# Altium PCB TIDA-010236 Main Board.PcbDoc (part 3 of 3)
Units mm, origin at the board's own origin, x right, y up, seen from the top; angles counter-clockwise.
Board outline 180 x 120 mm, 2 copper layers (Top Layer, Bottom Layer), stack 1.571 mm thick; 265 components, 145 nets, 704 pads, 547 vias.
Unrouted connection lines stored in the file: 155.
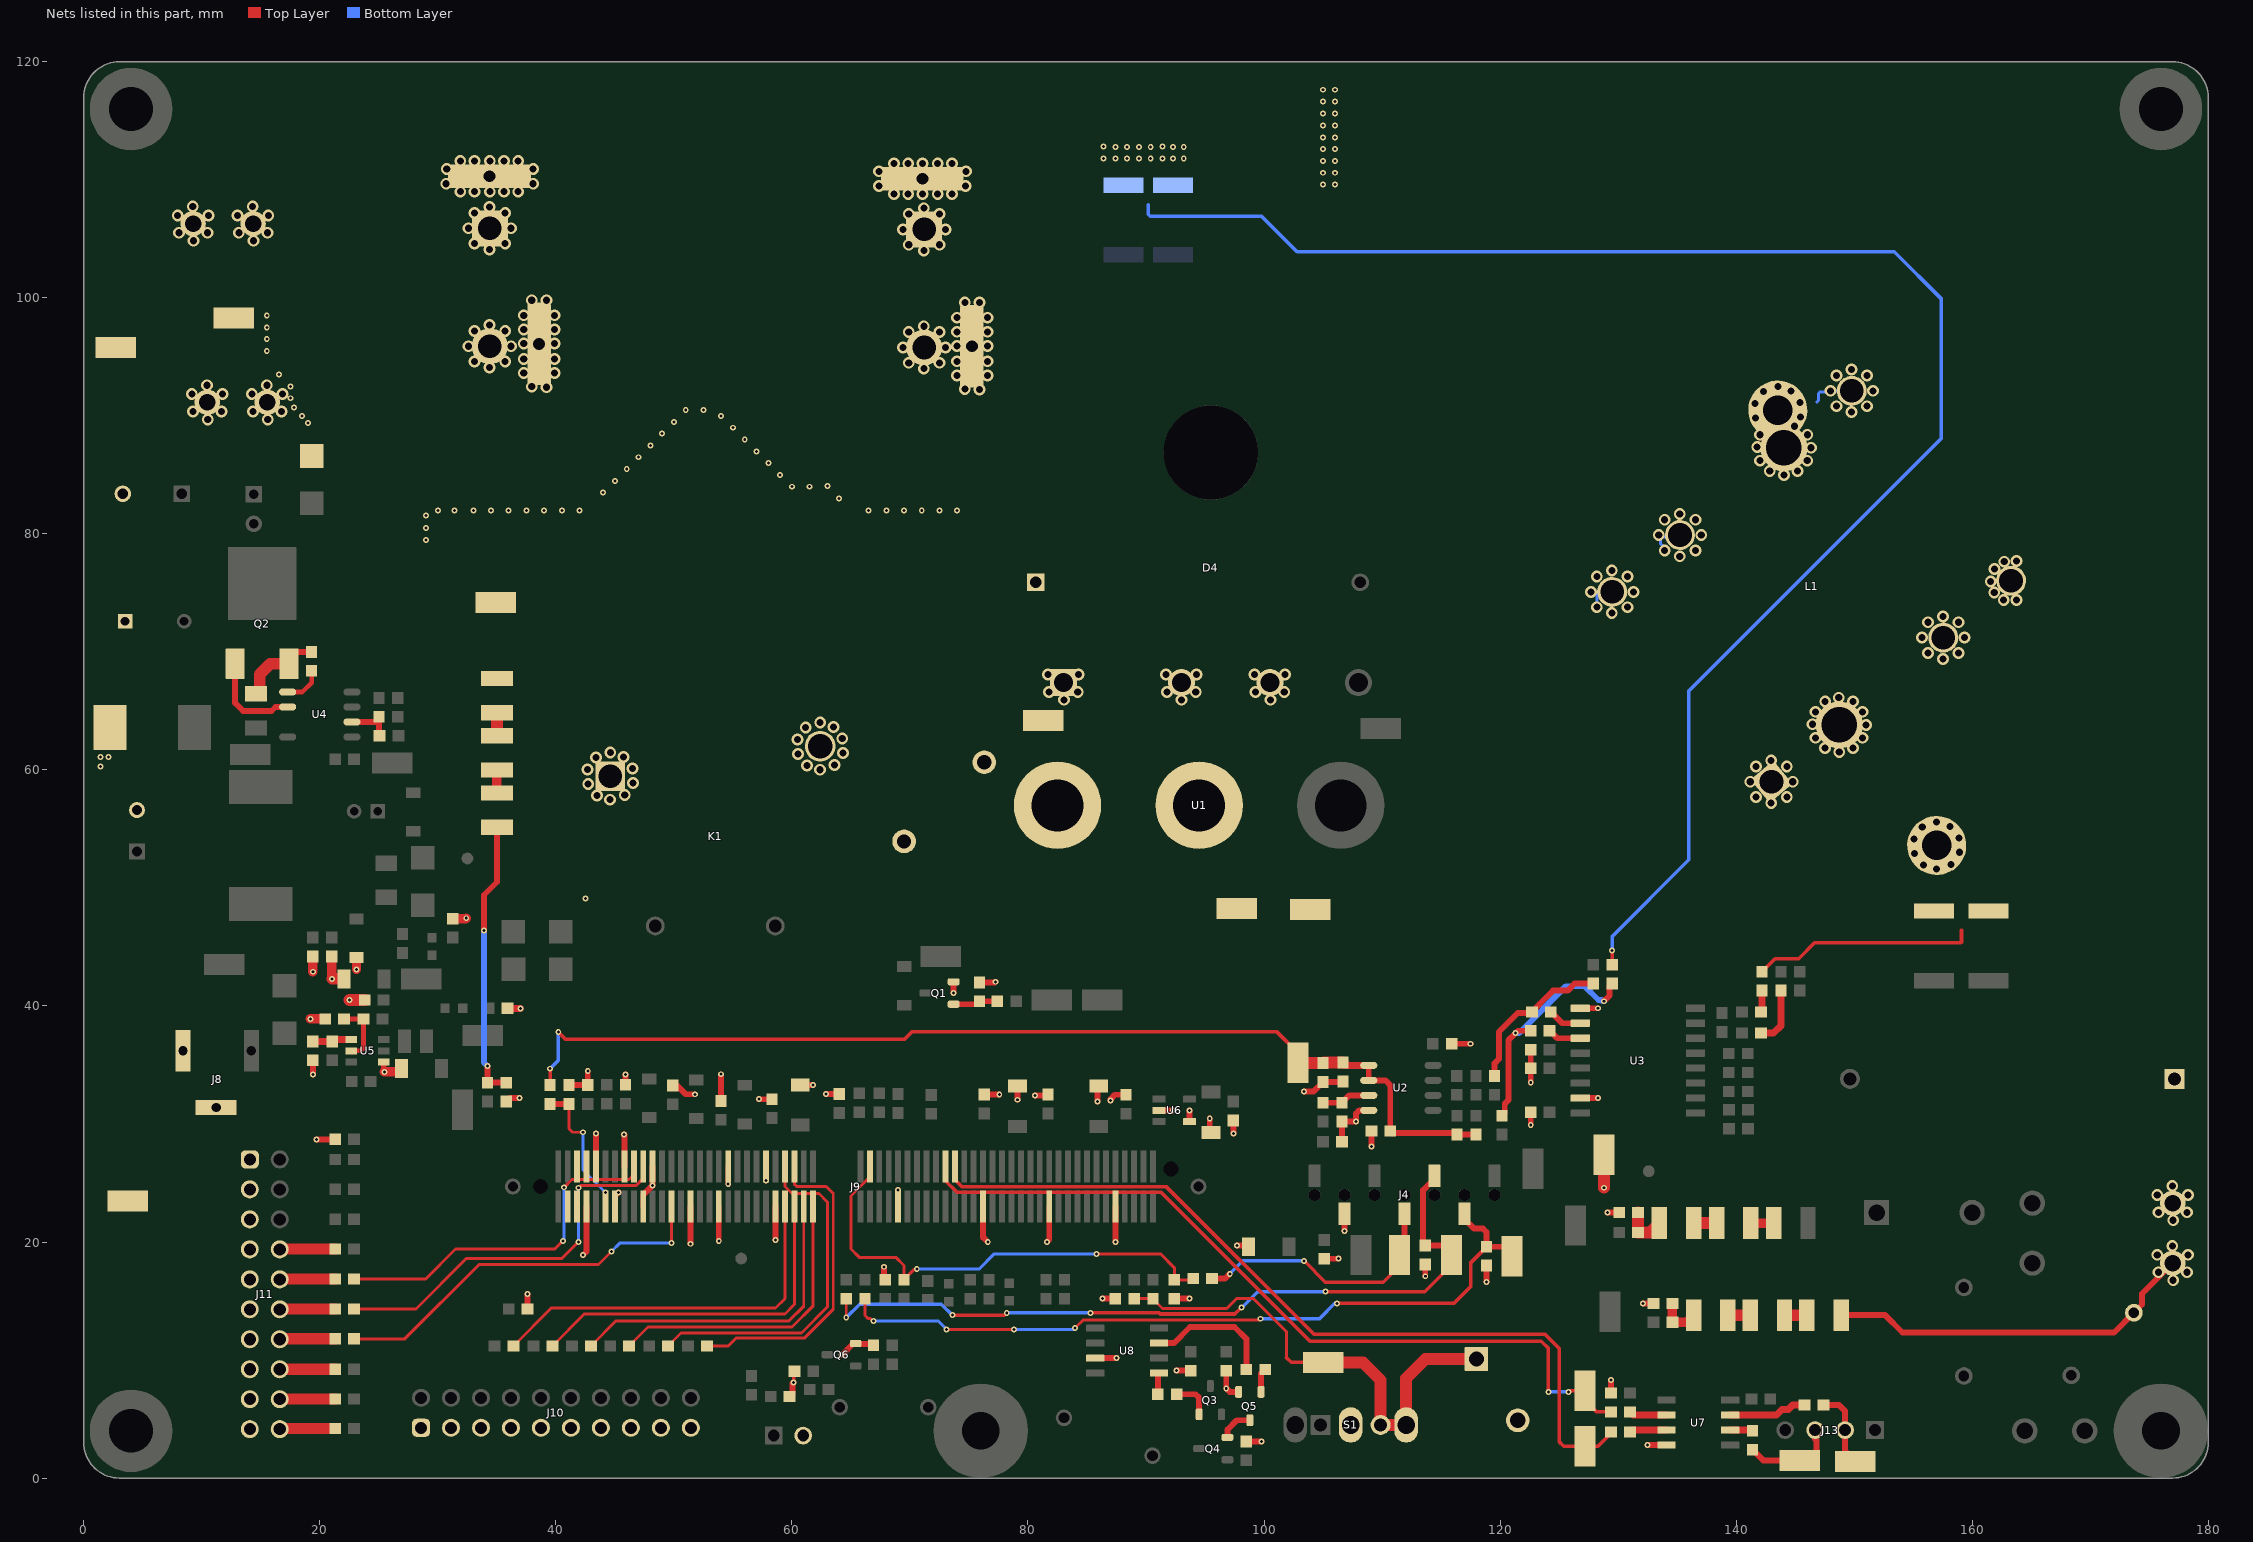
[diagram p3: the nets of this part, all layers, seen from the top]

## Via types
v1: diameter 1, hole 0.6, Top Layer to Bottom Layer, 286 vias
v2: diameter 0.5, hole 0.25, Top Layer to Bottom Layer, 261 vias

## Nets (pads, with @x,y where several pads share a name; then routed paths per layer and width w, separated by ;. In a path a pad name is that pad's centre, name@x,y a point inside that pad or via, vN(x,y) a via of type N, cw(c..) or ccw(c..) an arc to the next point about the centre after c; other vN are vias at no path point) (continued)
NetJ11_8: J11.8 R68.2 | length 4.7
  Top Layer w0.95: J11.8@16.6,19.38 16.62,19.4 R68.2@21.3,19.4
NetJ11_10: J11.10 R66.2 | length 4.7
  Top Layer w0.95: J11.10@16.6,16.84 16.627,16.867 R66.2@21.3,16.867
NetJ11_12: J11.12 R64.2 | length 4.7
  Top Layer w0.95: J11.12@16.6,14.3 16.633,14.333 R64.2@21.3,14.333
NetJ11_14: J11.14 R62.2 | length 4.7
  Top Layer w0.95: J11.14@16.6,11.76 16.64,11.8 R62.2@21.3,11.8
NetJ11_16: J11.16 R60.2 | length 4.7
  Top Layer w0.95: J11.16@16.6,9.22 R60.2@21.3,9.22
NetJ11_18: J11.18 R59.2 | length 4.7
  Top Layer w0.95: J11.18@16.6,6.68 16.62,6.7 R59.2@21.3,6.7
NetJ11_20: J11.20 R56.2 | length 4.7
  Top Layer w0.95: J11.20@16.6,4.14 16.66,4.2 R56.2@21.3,4.2
NetL1_1: L1.1 L1.2 L1.3 L1.4 L2.1 L4.2 R7.2 R8.2 | length 18.9
  Top Layer w0.3: L4.2@142.2,42.9 143.3,44 145.3,44 146.65,45.35 159.05,45.35 159.1,45.4 159.1,46.4
  other v1: 156.975,51.6 155.875,51.95 158.225,52 155.125,52.925 158.925,53.025 155.075,54.15 158.875,54.25 155.775,55.175 158.125,55.225 157,55.6 142.975,57.2 141.7,57.7 144.3,57.7 141.2,59 144.8,59 141.7,60.3 144.3,60.3 142.975,60.8 148.745,61.525 147.545,61.85 149.895,61.85 146.72,62.725 150.72,62.725 151.025,63.821 146.475,63.875 146.725,64.925 150.725,64.925 147.55,65.8 149.9,65.8 148.7,66.125 157.525,69.413 156.25,69.913 158.85,69.913 155.75,71.213 159.35,71.213 156.25,72.513 158.85,72.513 157.525,73.013 162.675,74.4 163.75,74.4 161.875,75.025 161.575,75.975 161.9,77.025 162.725,77.65 163.75,77.7
NetL4_1: L4.1 R6.1 | length 1.8
  Top Layer w0.6: R6.1@142.1,39.5 142.2,39.6 L4.1@142.2,41.3
NetL5_1: L5.1 R9.1 | length 4.9
  Top Layer w0.6: R9.1@142.1,37.7 143.176,37.7 143.8,38.324 L5.1@143.8,41.3
NetQ1_1: Q1.1 R2.1 R3.2 | length 3.8
  Top Layer w0.5: Q1.1@73.7,40.15 75.644,40.15 R3.2@75.893,40.4 R2.1@77.4,40.4
NetQ2_1: Q2.1 U4.6 | length 8.2
  Top Layer w0.5: Q2.1@12.82,69 12.82,65.68 13.5,65 15.9,65 16.235,65.335 U4.6@17.268,65.335
NetQ2_3: Q2.3 R1.1 R37.1 | length 7.1
  Top Layer w0.5: Q2.3@17.38,69 17.38,69.48 17.9,70 R1.1@19.3,70
  Top Layer w1: R37.1@14.9,66.45 14.9,68.1 15.8,69 Q2.3@17.38,69
NetQ3_1: Q3.1 R82.2 | length 3.4
  Top Layer w0.5: R82.2@92.6,7.1 94.2,7.1 94.5,6.8 Q3.1@94.5,5.4
NetQ4_2: Q4.2 Q5.3 | length 2.9
  Top Layer w0.5: Q4.2@96.9,3.45 96.9,4.1 97.7,4.9 Q5.3@98.8,4.9
NetQ5_1: Q5.1 R84.2 | length 2
  Top Layer w0.5: Q5.1@99.75,7.3 99.75,8.85 R84.2@100.1,9.2
NetR1_2: R1.2 U4.5 | length 3.4
  Top Layer w0.4: U4.5@17.268,66.605 18.505,66.605 19.3,67.4 R1.2@19.3,68.4
NetR10_1: R10.1 R11.2 U2.3 | length 4.1
  Top Layer w0.5: R10.1@105,31.8 R11.2@106.6,31.8 107.227,32.426 U2.3@108.875,32.426
NetR12_1: R12.1 R18.2 U5.5 | length 5.3
  Top Layer w0.4: R18.2@22.05,38.9 R12.1@23.7,38.9 23.7,36.434 23.466,36.2 U5.5@22.662,36.2
NetR14_2: R14.2 R15.1 | length 1.9
  Top Layer w0.8: R15.1@141.25,21.6 R14.2@143.2,21.6
NetR15_2: R15.2 R16.1 | length 1.9
  Top Layer w1: R16.1@136.4,21.6 R15.2@138.35,21.6
NetR16_2: R16.2 R17.1 R21.2 | length 3.8
  Top Layer w1: R21.2@131.7,22.5 R17.1@131.7,20.8 132.7,20.8 R16.2@133.5,21.6
NetR19_1: R19.1 R20.2 R85.1 | length 13.6
  Top Layer w0.5: R19.1@119.541,34.075 119.541,35.151 119.9,35.51 119.9,37.8 121.5,39.4 122.625,39.4 122.95,39.725 122.95,39.75 123.35,40.15 123.35,40.161 124.489,41.3 125.725,41.3 126.325,41.9 R20.2@127.9,41.9
NetR23_1: R23.1 R24.2 R86.1 | length 20
  Top Layer w0.5: R23.1@120.175,30.7 120.4,30.925 120.4,31.723 120.7,32.023 120.7,37.088 v2@121.306,37.694 ; 121.512,37.9 R86.1@122.6,37.9 ; v2(128.8,40.4) 129.275,40.875 129.275,41.675 R24.2@129.5,41.9
  Bottom Layer w0.5: v2(121.3,37.7) 121.6,37.7 125.575,41.675 127.174,41.675 128.342,40.507 128.59,40.507 128.697,40.4 v2(128.8,40.4)
NetR26_2: R26.2 R27.1 | length 1.9
  Top Layer w1: R27.1@144.1,13.8 R26.2@146,13.8
NetR27_2: R27.2 R28.1 | length 1.9
  Top Layer w1: R28.1@139.3,13.8 R27.2@141.2,13.8
NetR28_2: R28.2 R29.1 R30.2 | length 3.6
  Top Layer w0.8: R30.2@134.6,14.8 R29.1@134.6,13.2 135.8,13.2 R28.2@136.4,13.8
NetR31_2: R31.2 R32.1 | length 1.9
  Top Layer w1: R32.1@35,62.9 R31.2@35,64.85
NetR32_2: R32.2 R33.1 | length 2
  Top Layer w0.8: R33.1@35,58.05 R32.2@35,60
NetR33_2: R33.2 R34.1 R35.2 | length 23.8
  Top Layer w0.5: v2(33.9,46.4) 33.9,49.4 35,50.5 R33.2@35,55.15 ; v2(34.2,34.9) R34.1@34.2,33.5 R35.2@35.8,33.5
  Bottom Layer w0.5: v2(33.9,46.4) 33.9,35.2 v2(34.2,34.9)
NetR36_1: R36.1 R39.2 U4.2 | length 3.4
  Top Layer w0.5: U4.2@22.718,64.065 24.935,64.065 25,64 25,62.95 R36.1@25.05,62.9
NetR40_1: R40.1 R42.2 U5.4 | length 3.3
  Top Layer w0.6: R42.2@19.4,37 R40.1@21.039,37 21.189,37.15 U5.4@22.662,37.15
NetR78_2: R78.2 U7.7 | length 6.7
  Top Layer w0.6: U7.7@139.5,5.335 143.415,5.335 143.9,5.82 144.42,5.82 144.8,6.2 R78.2@145.8,6.2
NetR79_2: R79.2 U7.2 | length 3.2
  Top Layer w0.6: R79.2@131,5.6 131.265,5.335 U7.2@134.1,5.335
NetR80_1: R80.1 U7.3 | length 3.2
  Top Layer w0.6: R80.1@131,3.9 131.165,4.065 U7.3@134.1,4.065
NetR81_1: R81.1 U7.6 | length 1.9
  Top Layer w0.6: U7.6@139.5,4.065 141.335,4.065 R81.1@141.4,4
NetR82_1: R82.1 U8.5 | length 1.8
  Top Layer w0.5: R82.1@91,7.1 91,8.795 U8.5@91.1,8.895
NetR84_1: R84.1 U8.7 | length 11
  Top Layer w0.5: U8.7@91.1,11.435 92.367,11.435 93.732,12.8 97.5,12.8 98.5,11.8 R84.1@98.5,9.2
NetR85_2: R85.2 U3.10 | length 2.9
  Top Layer w0.5: R85.2@124.3,39.5 124.325,39.5 124.55,39.275 124.55,39.25 125.263,38.537 U3.10@126.811,38.537
NetR86_2: R86.2 U3.11 | length 2.9
  Top Layer w0.5: R86.2@124.2,37.9 124.225,37.9 124.858,37.267 U3.11@126.811,37.267
NEU_Filtered: C64.1 C69.2 D4.2 D4.3 J3.1 R26.1 | length 31.7
  Top Layer w0.5: R26.1@148.9,13.8 152.634,13.8 154.099,12.335 172.035,12.335 C69.2@173.703,14.003 174.4,14.7 174.4,15.62 J3.1@177,18.22
  other v1: 177.04,16.763 175.79,17.438 178.215,17.438 175.69,18.913 178.29,18.913 176.965,19.663 177.04,21.843 175.79,22.518 178.215,22.518 175.69,23.993 178.29,23.993 176.965,24.743 93,65.943 100.54,65.943 91.79,66.618 94.215,66.618 99.29,66.618 101.715,66.618 91.69,68.093 94.29,68.093 99.19,68.093 101.79,68.093
  other v2: 105,109.6 106,109.6 105,110.6 106,110.6 105.014,111.6 106.014,111.6 105,112.6 106,112.6 105,113.6 106,113.6 105.014,114.6 106.014,114.6 105,115.636 106,115.636 105,116.636 106,116.636 105.014,117.636 106.014,117.636
On/Off: J6.1 pad.2@112.04,4.5 R72.1 R75.2 S1.3 TP30.1 | length 42.3
  Top Layer w0.25: R75.2@89,15.2 R72.1@90.6,15.2 ; 101.9,10.2 101.9,12.4 99.1,15.2 97.664,15.2 96.839,14.375 91.4,14.375 R72.1@90.6,15.175 ; R72.1@90.6,15.175 R72.1@90.6,15.2 ; R72.1@90.6,15.175 R72.1@90.6,15.2
  Top Layer w0.3: 101.9,10.2 102.3,9.8 TP30.1@105.039,9.8
  Top Layer w1: TP30.1@105.039,9.8 108.375,9.8 109.88,8.295 S1.3@109.88,4.5 pad.2@112.04,4.5 112.04,8.46 113.665,10.085 J6.1@118,10.085
PB+: C1.2 C2.2 C3.1 C4.1 D12.2 J5.1 K1.1 R31.1 RT1.1 TP2.1 TP3.1
  other v1: 44.585,57.48 43.485,57.83 45.835,57.88 42.735,58.805 46.535,58.905 42.685,60.03 46.485,60.13 43.385,61.055 45.735,61.105 44.61,61.48 10.5,89.7 15.58,89.7 9.25,90.375 11.675,90.375 14.33,90.375 16.755,90.375 9.15,91.85 11.75,91.85 14.23,91.85 16.83,91.85 75.9,92.225 74.65,92.275 39.2,92.425 37.95,92.475 10.425,92.6 15.505,92.6 73.975,93.425 76.575,93.425 37.275,93.625 39.875,93.625 71.175,94 34.375,94.1 69.9,94.5 72.5,94.5 33.1,94.6 35.7,94.6 73.975,94.625 76.575,94.625 37.275,94.825 39.875,94.825 69.4,95.8 73,95.8 32.6,95.9 36.2,95.9 73.975,95.925 76.575,95.925 37.275,96.125 39.875,96.125 69.9,97.1 72.5,97.1 73.975,97.125 76.575,97.125 33.1,97.2 35.7,97.2 37.275,97.325 39.875,97.325 71.175,97.6 34.375,97.7 73.975,98.325 76.575,98.325 37.275,98.525 39.875,98.525 74.65,99.6 75.9,99.6 37.95,99.8 39.2,99.8
  other v2: 29,79.5 29,80.5 29,81.55 30,82 31.4,82 33,82 34.5,82 35.996,82 37.5,82 39,82 40.5,82 42,82 66.5,82 68,82 69.505,82 71,82 72.5,82 74,82 64,83 44,83.5 60,84 61.5,84 63,84.05 45,84.5 59,85 46,85.5 58,86 47,86.5 57,87 48,87.5 56,88 49,88.5 55,89 19,89.4 50,89.5 18.5,90 54,90 51,90.5 52.5,90.5 17.8,90.7 17.5,91.5 17.5,92.5 16.54,93.5 15.5,95.5 15.5,96.5 15.5,97.5 15.5,98.5
PB-: C1.1 C2.1 C3.2 C4.2 C6.2 C7.2 C9.2 C13.2 C15.2 C16.2 C17.2 C19.2 C20.1 C22.2 C23.1 C24.2 C26.2 C27.2 C28.2 C29.2 C34.2 C35.2 C36.2 C37.1 C38.2 C39.2 C40.2 C41.2 C42.2 C43.2 C44.2 C45.2 C46.1 C47.1 C48.2 C49.2 C50.2 C51.2 C52.2 C53.2 C54.2 C56.2 C58.2 C59.2 C61.2 C62.2 C63.2 C65.1 C66.1 C67.1 D15.2 D16.2 J4.6 J6.2 J7.1 J8.2 J8.3 J9.7 J9.10 J9.13 J9.16 J9.19 J9.22 J9.29 J9.35 J9.38 J9.46 J9.47 J9.65 J9.83 J9.97 J9.111 J10.1 J10.3 J10.5 J10.7 J10.9 J10.11 J10.13 J10.15 J10.17 J10.19 J11.1 J11.3 J11.5 J11.7 J11.9 J11.11 J11.13 J11.15 J11.17 J11.19 J12.2 Q1.2 Q5.2 Q6.2 R3.1 R4.2 R5.2 R11.1 R18.1 R21.1 R24.1 R30.1 R35.1 R42.1 R43.1 R44.1 R45.2 S1.2 TP8.1 TP28.1 TP29.1 U2.4 U3.9 U3.15 U5.1 U6.2 U6.4 U7.4 U8.3 | length 266.3
  Top Layer w0.3: v2(60.144,8.1) 60.144,8.991 C61.2@60.207,9.055 ; R24.1@129.5,43.5 v2(129.5,44.7)
  Top Layer w0.5: v2(19.4,34.192) R42.1@19.4,35.4 ; v2(19.7,28.7) C65.1@21.3,28.7 ; U5.1@25.412,35.25 25.412,34.459 v2(25.462,34.409) ; R35.1@35.8,31.9 36.1,32.2 v2(36.9,32.2) ; C63.2@37.6,14.333 v2(37.6,15.6) ; C45.2@41.1,33.3 C24.2@42.7,33.3 v2(42.7,34.5) ; v2(42.3,18.9) 42.6,19.2 J9.7@42.6,23 ; J9.10@43.4,26.4 v2(43.4,29.2) ; J9.13@45,23 45,23.9 v2(45.3,24.2) ; v2(45.775,29.125) 45.8,29.1 J9.16@45.8,26.4 ; C29.2@45.9,33.317 v2(45.9,34.2) ; J9.19@47.4,23 47.4,24 v2(48.2,24.8) J9.22@48.2,26.4 ; C28.2@49.9,33.275 50.242,33.275 51,32.517 v2(51.8,32.517) ; v2(51.4,19.85) J9.29@51.4,23 ; v2(53.8,20.1) J9.35@53.8,23 ; C22.2@54,31.956 v2(54,34.219) ; v2(54.6,24.9) J9.38@54.6,26.4 ; v2(57.2,32.106) 57.206,32.1 C47.1@58.3,32.1 ; v2(57.8,25.2) J9.46@57.8,26.4 ; v2(58.6,20.176) J9.47@58.6,23 ; C58.2@59.8,6.901 59.825,6.901 60.05,7.126 60.05,8.006 v2(60.144,8.1) ; C46.1@60.7,33.3 60.717,33.317 v2(61.8,33.317) ; v2(62.9,32.54) C23.1@64,32.54 ; v2(64.2,10.45) 64.25,10.45 65.2,11.4 Q6.2@65.4,11.4 65.45,11.35 66.805,11.35 C62.2@66.905,11.25 ; v2(67.8,17.9) 67.8,16.9 C44.2@67.9,16.8 ; J9.65@69,23 v2(69,24.4) ; v2(73.7,41.1) Q1.2@73.7,42.05 ; R3.1@75.893,42 77.183,42 v2(77.233,42.05) ; J9.83@76.2,23 76.2,20.395 v2(76.595,20) ; C53.2@76.3,32.5 v2(77.567,32.5) ; v2(79.1,32.057) C50.2@79.1,33.2 ; v2(80.6,32.426) 81.626,32.426 C51.2@81.7,32.5 ; v2(81.6,20) 81.8,20.2 J9.97@81.8,23 ; U8.3@85.7,10.165 v2(87.5,10.165) ; v2(85.9,31.9) 85.9,33.1 C42.2@86,33.2 ; v2(86.3,15.2) C49.2@87.4,15.2 ; v2(87,32) 87,32.11 87.365,32.475 C52.2@88.3,32.475 C52.2@88.275,32.5 ; v2(87.4,20) J9.111@87.4,23 ; U6.2@91.1,31.156 v2(92.3,31.156) ; C27.2@92.4,15.2 v2(93.7,15.2) ; v2(92.6,9.1) C59.2@93.8,9.1 ; U6.4@93.7,30.206 v2(93.7,31.156) ; v2(95.4,30.463) 95.4,29.4 C41.2@95.5,29.3 ; C56.2@96.8,9.1 v2(96.8,7.6) 97.1,7.3 Q5.2@97.85,7.3 ; v2(97.4,29.2) C43.2@97.4,30.3 ; v2(97.7,19.7) 98.6,19.7 C6.2@98.7,19.6 ; C48.2@98.5,3.1 v2(99.8,3.1) ; v2(103.4,32.762) 104.201,32.762 C16.2@105,33.561 106.661,33.561 C26.2@106.7,33.6 ; C7.2@105.1,18.58 106.28,18.58 v2(106.3,18.6) ; C13.2@106.6,28.5 R11.1@106.6,30.2 v2(107.8,30.2) 107.8,30.875 108.082,31.156 U2.4@108.875,31.156 ; v2(106.82,20.92) J4.6@106.82,22.397 ; v2(109.1,28.1) C17.2@109.1,29.4 ; v2(113.665,17.1) C66.1@113.665,18.1 ; C9.2@115.9,36.8 v2(117.5,36.8) ; v2(118.85,16.6) C67.1@118.85,18 ; v2(122.6,29.9) C15.2@122.6,31 ; v2(122.6,33.5) 122.6,33.696 C19.2@122.6,34.727 C20.1@122.6,36.3 ; U3.15@126.811,32.187 v2(128.3,32.187) ; U3.9@126.811,39.807 v2(128.3,39.807) ; v2(129.1,22.5) R21.1@130.1,22.5 ; C54.2@129.4,7.2 v2(129.4,8.3) ; v2(132.1,14.8) R30.1@133,14.8 ; v2(132.5,2.795) 132.5,2.8 132.505,2.795 U7.4@134.1,2.795
  Top Layer w0.6: R43.1@35.9,39.8 v2(37,39.8)
  Top Layer w0.8: v2(19.2,38.9) R18.1@20.45,38.9 ; v2(19.4,42.9) R44.1@19.4,44.2 ; C40.2@21,44.2 21,42.339 v2(21.039,42.3) ; v2(23.1,43.1) D15.2@23.1,44.1 ; v2(25.462,34.409) 26.75,34.409 26.9,34.559 C34.2@26.9,34.701 ; R45.2@31.25,47.4 32.363,47.4 v2(32.4,47.437)
  Top Layer w1: v2(21.039,42.3) C35.2@22.05,42.3 ; v2(22.5,40.5) C36.2@23.8,40.5 ; v2(128.8,24.6) TP28.1@128.8,27.4
  Bottom Layer w0.3: 90.2,107.9 90.2,107.1 90.4,106.9 99.8,106.9 102.8,103.9 153.407,103.9 157.4,99.907 157.4,88.093 136,66.693 136,52.388 129.5,45.888 v2(129.5,44.7)
  other v1: 71.175,104 34.375,104.1 69.9,104.5 72.5,104.5 33.1,104.6 35.7,104.6 9.3,104.843 14.38,104.843 8.05,105.518 10.475,105.518 13.13,105.518 15.555,105.518 69.4,105.8 73,105.8 32.6,105.9 36.2,105.9 7.95,106.993 10.55,106.993 13.03,106.993 15.63,106.993 69.9,107.1 72.5,107.1 33.1,107.2 35.7,107.2 71.175,107.6 34.375,107.7 9.225,107.743 14.305,107.743 68.65,108.8 69.85,108.8 71.05,108.8 72.35,108.8 73.55,108.8 31.9,109 33.1,109 34.4,109 35.6,109 36.8,109 67.375,109.475 74.7,109.475 30.7,109.675 38.075,109.675 67.375,110.725 74.75,110.725 30.75,110.925 38.075,110.925 68.65,111.4 69.85,111.4 71.05,111.4 72.35,111.4 73.55,111.4 31.9,111.6 33.1,111.6 34.4,111.6 35.6,111.6 36.8,111.6
  other v2: 42.5,49.1 1.4,60.3 1.4,61.1 2.1,61.1 86.4,111.814 87.4,111.8 88.4,111.8 89.4,111.8 90.4,111.8 91.4,111.814 92.3,111.814 93.2,111.814 86.4,112.814 87.4,112.8 88.4,112.8 89.4,112.8 90.4,112.8 91.4,112.814 92.3,112.8 93.2,112.8
PBGaN: C5.1 D4.1 K1.2 RT1.2 TP1.1 U1.1
  other v1: 62.365,60.02 61.265,60.37 63.615,60.42 60.515,61.345 64.315,61.445 60.465,62.57 64.265,62.67 61.165,63.595 63.515,63.645 62.39,64.02 83.04,65.943 81.79,66.618 84.215,66.618 81.69,68.093 84.29,68.093
PWM_1A: J9.49 R54.1 | length 32.5
  Top Layer w0.25: R54.1@36.4,11.2 39.6,14.4 58.6,14.4 59.4,15.2 J9.49@59.4,23
PWM_1B: J9.51 R52.1 | length 30.2
  Top Layer w0.25: R52.1@39.7,11.2 42.4,13.9 59.4,13.9 60.2,14.7 J9.51@60.2,23
PWM_2A: J9.53 R51.1 | length 27.9
  Top Layer w0.25: R51.1@42.962,11.2 45.062,13.3 59.733,13.3 61,14.567 J9.53@61,23
PWM_2B: J9.55 R50.1 | length 25.4
  Top Layer w0.25: R50.1@46.2,11.2 47.8,12.8 60,12.8 61.8,14.6 J9.55@61.8,23
PWM_3A: J9.50 R49.1 | length 29.6
  Top Layer w0.25: R49.1@49.5,11.2 50.6,12.3 60.8,12.3 63,14.5 63,23.4 62.3,24.1 60,24.1 59.4,24.7 J9.50@59.4,26.4
PWM_3B: J9.52 R48.1 | length 26.9
  Top Layer w0.25: R48.1@52.8,11.2 54.6,11.2 55.25,11.85 61.05,11.85 63.5,14.3 63.5,24.1 62.9,24.7 60.4,24.7 60.2,24.9 J9.52@60.2,26.4
PWM_4A: C66.2 J4.3 R55.2 TP4.1 | length 65.6
  Top Layer w0.25: v2(64.6,13.6) R55.2@64.6,15.2
  Top Layer w0.3: v2(73.6,13.8) 78,13.8 v2(78.2,14) ; v2(85.3,14) 91.103,14 91.203,13.9 97.517,13.9 98.06,14.443 v2(98.1,14.443) ; v2(105.2,15.8) 113.625,15.8 115.9,18.074 TP4.1@115.9,18.9
  Top Layer w0.5: J4.3@114.44,25.603 114.44,25.22 114.18,24.96 114.042,24.96 113.48,24.398 113.48,19.885 C66.2@113.665,19.7 115.261,19.7 115.9,19.061 TP4.1@115.9,18.9
  Bottom Layer w0.3: v2(64.6,13.6) 65.741,14.741 72.659,14.741 v2(73.6,13.8) ; v2(78.2,14) v2(85.3,14) ; v2(98.1,14.443) 99.457,15.8 v2(105.2,15.8)
PWM_4B: C67.2 J4.2 R57.2 TP5.1 | length 65.3
  Top Layer w0.25: R57.2@66.2,15.2 66.2,13.767 66.432,13.534 66.603,13.534 66.837,13.3 v2(66.905,13.3) ; v2(73.1,12.6) v2(78.8,12.6) ; v2(83.979,12.705) 84.674,13.4 99.6,13.4 v2(99.7,13.5)
  Top Layer w0.3: v2(106.2,14.8) 116.1,14.8 117.5,16.2 117.5,18.225 118.85,19.575 C67.2@118.85,19.6
  Top Layer w0.5: J4.2@116.98,22.397 116.98,21.955 117.803,21.132 118.557,21.132 118.85,20.84 C67.2@118.85,19.6 120.373,19.6 121.012,18.961 TP5.1@121.012,18.8
  Bottom Layer w0.25: v2(66.905,13.3) 72.4,13.3 v2(73.1,12.6) ; v2(78.8,12.6) 83.874,12.6 v2(83.979,12.705)
  Bottom Layer w0.3: v2(99.7,13.5) 104.7,13.5 106,14.8 v2(106.2,14.8)
REF1V65: C16.1 C17.1 C25.2 C26.1 R25.1 R47.2 TP14.1 U2.1 U2.2 | length 90.3
  Top Layer w0.3: R47.2@39.5,33.3 v2(39.5,34.684) ; v2(40.2,37.8) 40.8,37.2 69.551,37.2 70.151,37.8 100.851,37.8 101.1,37.8 102.9,36 TP14.1@102.9,35.2
  Top Layer w0.5: U2.1@108.875,34.966 U2.2@108.875,33.696 110.3,33.696 110.7,33.296 C17.1@110.7,29.4 110.9,29.2 110.95,29.25 116.2,29.25 R25.1@116.35,29.1 C25.2@117.953,29.1
  Top Layer w0.6: C26.1@106.619,35.119 106.772,34.966 U2.1@108.875,34.966
  Top Layer w1: TP14.1@102.9,35.2 102.939,35.161 C16.1@105,35.161 105.039,35.2 C26.1@106.7,35.2
  Bottom Layer w0.3: v2(39.5,34.684) 40.2,35.384 v2(40.2,37.8)
REF1V65_AD: C45.1 J9.11 R47.1 | length 12.1
  Top Layer w0.25: C45.1@41.1,31.7 41.1,29.6 41.4,29.3 v2(42.3,29.3) ; J9.11@44.2,23 v2(44.2,24.2)
  Top Layer w0.5: R47.1@39.5,31.7 C45.1@41.1,31.7
  Bottom Layer w0.25: v2(42.3,29.3) 42.3,26.1 v2(44.2,24.2)
SWNODE1: L1.5 L1.6 L1.7 L1.8 L2.2 TP6.1 TP7.1 U1.2 | length 15.5
  Top Layer w0.25: v1(127.698,75.091) v1@127.7,75.089 ; v1(133.45,79.9) 133.568,79.782 133.568,79.741 v1@133.594,79.716 ; v1(133.95,78.6) v1@133.95,78.803 ; L1.7@135.055,79.741 L1.7@135.222,79.908 ; v1@141.993,88.021 143.31,88.021 144.031,87.3 L1.6@143.542,86.811 ; v1@147.919,92.044 v1(148,92.125) v1@148.002,92.123 ; L1.5@149.775,92.123 L1.5@149.777,92.121
  Bottom Layer w0.25: v1(127.698,75.091) 127.7,75.089 128.198,75.089 ; v1(128.198,73.791) 128.198,75.087 L1.8@129.476,75.087 ; v1(133.45,79.9) 133.568,79.782 v1@133.568,79.741 ; v1(133.95,78.6) 133.95,78.803 133.594,79.159 133.594,79.716 v1@133.568,79.741 ; L1.7@135.222,79.908 135.055,79.741 v1@133.568,79.741 ; L1.6@143.364,87.967 144.031,87.3 L1.6@143.542,86.811 ; 146.844,91.157 146.987,91.3 146.987,91.897 147.134,92.044 147.919,92.044 v1(148,92.125) 148.002,92.123 149.775,92.123 L1.5@149.777,92.121
  other v1: 129.473,73.291 130.798,73.791 131.298,75.091 128.198,76.391 130.798,76.391 129.473,76.891 135.225,78.1 136.55,78.6 137.05,79.9 133.95,81.2 136.55,81.2 135.225,81.7 144.056,85.004 142.856,85.329 145.206,85.329 142.031,86.204 146.031,86.204 146.336,87.3 141.786,87.354 142.036,88.404 146.036,88.404 144.95,89.125 141.66,89.821 145.46,89.921 149.775,90.325 148.5,90.825 151.1,90.825 141.61,91.046 145.41,91.146 142.31,92.071 144.66,92.121 151.6,92.125 143.535,92.496 148.5,93.425 151.1,93.425 149.775,93.925
TCK: J9.5
TDI: J9.8
TDO: J9.6
TEMP_L: J4.4 R83.1 TP10.1 | length 22.4
  Top Layer w0.3: v2(103.4,18.4) 105.2,16.6 110.1,16.6 111.5,18 TP10.1@111.5,18.9
  Top Layer w0.5: R83.1@95.6,16.9 96.7,16.9 v2(97.1,17.3) ; TP10.1@111.5,18.9 111.9,19.3 J4.4@111.9,22.397
  Bottom Layer w0.3: v2(97.1,17.3) 98.2,18.4 v2(103.4,18.4)
TEMP_L_Filter: C27.1 J9.60 R46.1 R83.2 | length 40.9
  Top Layer w0.25: J9.60@66.6,26.4 66.6,25.5 65,23.9 65,19.4 65.7,18.7 68.8,18.7 69.5,18 R46.1@69.5,16.825 ; R46.1@69.5,16.8 R46.1@69.5,16.825 ; v2(70.577,17.7) 70.529,17.652 70.327,17.652 R46.1@69.5,16.825 ; v2(85.8,19) 91.225,19 92.4,17.825 C27.1@92.4,16.8 93.9,16.8 R83.2@94,16.9
  Bottom Layer w0.25: v2(70.577,17.7) 75.841,17.7 77.141,19 v2(85.8,19)
TMS: J9.3
UART_RX: J13.2 R78.1 TP31.1 | length 7.1
  Top Layer w0.3: TP31.1@149.57,1.33 TP31.1@149.9,1
  Top Layer w0.5: R78.1@147.4,6.2 148.7,6.2 149.24,5.66 J13.2@149.24,4.065 149.24,2.26 TP31.1@150.1,1.4
UART_RX_MCU: J9.76 R79.1 TP32.1 | length 68.4
  Top Layer w0.3: J9.76@73,26.4 73,25.2 74,24.2 91.3,24.2 103.9,11.6 123.5,11.6 124.1,11 v2(124.1,7.3) ; v2(125.8,7.3) 125.9,7.4 TP32.1@127.2,7.4 127.2,6.6 128.2,5.6 R79.1@129.4,5.6
  Bottom Layer w0.3: v2(124.1,7.3) v2(125.8,7.3)
UART_TX: J13.3 R81.2 TP34.1 | length 8.3
  Top Layer w0.5: R81.2@141.4,2.4 142.3,1.5 TP34.1@145.4,1.5 146.7,1.5 146.8,1.6 146.8,3.2 146.7,3.3 J13.3@146.7,4.065
UART_TX_MCU: J9.78 R80.2 TP33.1 | length 71.4
  Top Layer w0.3: J9.78@73.7,26.3 J9.78@73.8,26.4 73.8,25.3 74.4,24.7 91.7,24.7 104.2,12.2 123.8,12.2 125,11 125,3.1 125.4,2.7 TP33.1@127.2,2.7 128.3,2.7 129.4,3.8 R80.2@129.4,3.9
Vu: J9.25 R62.1 | length 33.4
  Top Layer w0.25: R62.1@22.9,11.8 27.2,11.8 33.5,18.1 43.6,18.1 v2(44.7,19.2) ; v2(49.8,19.9) J9.25@49.8,23
  Bottom Layer w0.25: v2(44.7,19.2) 45.4,19.9 v2(49.8,19.9)
Vv: J9.20 R64.1 | length 33.2
  Top Layer w0.25: R64.1@23.167,14.6 R64.1@22.9,14.333 28.133,14.333 32.4,18.6 40.5,18.6 v2(41.9,20) ; v2(41.9,24.6) 42.1,24.8 46.8,24.8 47.4,25.4 J9.20@47.4,26.4
  Bottom Layer w0.25: v2(41.9,20) v2(41.9,24.6)
Vw: J9.18 R66.1 | length 30.7
  Top Layer w0.25: R66.1@22.9,16.867 28.967,16.867 31.5,19.4 39.9,19.4 v2(40.6,20.1) ; v2(40.7,24.637) 41.362,25.3 46.2,25.3 46.6,25.7 J9.18@46.6,26.4
  Bottom Layer w0.25: v2(40.6,20.1) 40.7,20.2 v2(40.7,24.637)
pads on no net: D4. FID1.1 FID2.1 FID3.1 H2.1 H3.1 H6.1 J4. J4.1 J9.1 J9.2 J9.4 J9.24 J9.30 J9.31 J9.32 J9.33 J9.36 J9.37 J9.39 J9.40 J9.41 J9.42 J9.43 J9.44 J9.59 J9.61 J9.63 J9.64 J9.66 J9.68 J9.70 J9.71 J9.72 J9.73 J9.74 J9.75 J9.77 J9.79 J9.80 J9.81 J9.85 J9.86 J9.87 J9.88 J9.90 J9.91 J9.92 J9.93 J9.94 J9.95 J9.96 J9.100 J9.102 J9.103 J9.104 J9.106 J9.107 J9.108 J9.109 J9.110 J9.113 J9.114 J9.115 J9.116 J9.117 J9.120 J9.181 J9.182 J9.185 J9.186 LBL1.0 R68.1 R71.1 S1.1 U3.4 U3.14 U4.3 U8.1 U8.8

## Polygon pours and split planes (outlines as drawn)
NetL1_1 on Top Layer "NetL1_1_daa" (solid, pour order 241): 140.4,63.8 140.4,45.7 163.3,45.7 164.25,46.65 164.25,78.225 163.575,78.9 162.756,78.9 155.5,78.9
EARTH on Top Layer "Top Layer-EARTH 1" (solid, pour order 238): 157.5,8.6 158.5,9.6 178.94,9.6 179.9,8.64 179.9,2.06 178.04,0.2 159,0.2 157.5,1.7
PB+ on Top Layer "Top Layer-PB+" (solid, pour order 235): 28.1,79.5 28.6,79 32,75.6 32,68 33,67 37.949,67 38,67 40.6,64.4 40.6,59 43.1,56.5 47.9,51.7 70.26,51.7 71,52.387 71,54.9 68.9,57 58.3,57 55.8,59.5 55.8,70.6 55.8,75.6 55.8,77.2 57.6,79 76.6,79 78,80.4 78,82 77.5,82.5 65.3,82.5 63.65,84.15 63.3,84.5 60.6,84.5 54.1,91 50.8,91 42.5,82.7 28.6,82.7 28.1,82.2
5V on Top Layer "Top Layer-5V" (solid, pour order 233): 32.3,36.4 37.2,36.4 37.6,36.8 37.6,38 36.9,38.7 31.4,38.7 31.1,39 31.1,40.4 31,40.5 28.9,40.5 28.5,40.1 28.5,34.192 28.85,33.842 30.908,33.842 31.75,34.684 31.75,35.85
15V on Top Layer "Top Layer-15V" (solid, pour order 231): 24.5,37.124 24.76,36.864 25.964,36.864 26.2,37.1 26.2,40.5 26.8,41.1 37.2,41.1 37.5,41.4 37.5,44.5 37.1,44.9 24.9,44.9 24.5,44.5 24.5,43.35 24.5,38.844
Idc on Top Layer "Top Layer-PB-" (solid, pour order 28): 109,53.1 114.325,58.425 114.325,77.075 111.7,79.7 107.9,79.7 106.175,77.975 106.175,63.975 102,59.8 102,55.4 104.3,53.1
PB- on Top Layer "Top Layer-PB- 1" (solid, pour order 227): 0.806,55.794 1.4,55.2 5.9,55.2 6.5,55.8 6.5,57.5 4.5,59.5 4.5,98.7 9,103.2 12.2,103.2 79.2,103.2 83.3,107.3 94.404,107.3 95,107.896 95,117.8 93.8,119 83.1,119 17.5,119 8.8,110.3 0.8,102.3 0.8,61 0.806,60.994
NetC39_1 on Top Layer "Top Layer-NetC39_1 1" (solid, pour order 219): 17.7,50.2 10.8,50.2 6.4,54.6 2.05,54.6 0.9,53.45 0.9,41.8 1.9,40.8 18.005,40.8 18.505,41.3 18.5,44.8 18.976,45.276 19.2,45.276 19.2,46.6 19.1,46.7 6.075,46.7 5.6,47.175 5.6,47.9 5.967,48.267 6.533,48.267 7.6,47.2 17.8,47.2 18.4,47.8 18.4,49.5
NetD11_2 on Top Layer "Top Layer-NetD11_2" (solid, pour order 200): 12.6,34.409 13.734,33.275 18.03,33.275 18.3,33.545 18.3,39.112 17.912,39.5 13,39.5 12.6,39.1
NetC39_1 on Top Layer "Top Layer-NetC39_1" (solid, pour order 198): 21.597,45.276 21.92,45.6 27.6,45.6 27.9,45.9 27.9,46.9 28.5,47.5 29.93,47.5 30.186,47.756 30.1,47.842 30.1,49.2 29.7,49.6 24.9,49.6 23.175,47.875 19.515,47.875 18.3,46.66 18.3,45.5 18.524,45.276
PBGaN on Top Layer "Top Layer-PBGaN" (solid, pour order 145): 86.4,72.2 80.6,78 74.3,78 59.9,78 58,76.1 58,59.8 59.6,58.2 70.4,58.2 76.1,52.5 84.865,52.5 86.4,54.116
NEU_Filtered on Top Layer "Top Layer-NEU_Filtered" (solid, pour order 137): 93.3,103.8 84.9,95.4 84.9,80.9 91.291,74.509 91.291,66.084 92.075,65.3 101.575,65.3 102.4,66.125 102.4,81.5 126.8,105.9 159.1,105.9 169.3,95.7 169.3,31.4 173,27.7 173,14.7 174.2,13.5 178.38,13.5 179.5,14.474 179.5,102.4 162.9,119 102,119 100,117 100,110.5
LINE_Filtered1 on Top Layer "Top Layer-LINE_Filtered1" (solid, pour order 123): 164,44 163.5,44.5 149.7,44.5 147.62,42.42 147.62,21.58 149,20.2 154.25,20.2 155.5,21.589 155.5,26.9 157.1,28.5 163.5,28.5 164,29
LINE_Filtered on Top Layer "Top Layer-LINE_Filtered" (solid, pour order 117): 167.5,17 167.5,25.5 167,26 159.5,26 158.5,25 158.5,16 159,15.5 165.7,15.5
SWNODE1 on Top Layer "Top Layer-SWNODE1" (solid, pour order 115): 133,100.4 117.4,84.8 117.4,57.2 110.3,50.1 102.335,50.1 98.6,53.835 98.6,60.1 97.6,61.1 91.4,61.1 90.4,60.1 90.4,45.8 93.2,43 119.8,43 126.9,50.1 128.4,50.1 132.3,54 132.3,69 154,90.7 154,95.4 149,100.4
EARTH1 on Top Layer "Top Layer-EARTH" (solid, pour order 92): 84.2,5.4 84.2,1.3 83.4,0.5 70.3,0.5 69.5,1.3 69.5,5.3 72.5,8.3 81.3,8.3
PB+ on Top Layer "Top Layer-PB+ 1" (solid, pour order 90): 15.6,100.2 11.2,100.2 8.5,97.5 8.5,88.567 11.667,85.4 20.2,85.4 20.4,85.6 20.4,88.6 18,91 18,92.8 16,94.8 16,99.8
PB- on Top Layer "Top Layer-PB- 3" (solid, remove dead copper, pour order 72): 10.8,38.7 10.8,35.4 15.4,30.8 15.4,1.1 14.8,0.5 10,0.5 9,1.5 9,7.9 7.4,9.5 1.7,9.5 0.8,10.4 0.8,39.1 1.7,40 9.5,40
EARTH on Bottom Layer "Top Layer-EARTH 1" (solid, pour order 163): 157.5,8.6 158.5,9.6 178.94,9.6 179.9,8.64 179.9,2.06 178.04,0.2 159,0.2 157.5,1.7
PB+ on Bottom Layer "Bottom Layer-PB+" (solid, pour order 237): 8.5,87 10.1,85.4 21.8,85.4 28.2,79 32,75.2 32,68.05 33.05,67 37.9,67 40.6,64.3 40.6,59 43.1,56.5 47.9,51.7 70.26,51.7 71,52.387 71,54.9 68.9,57 58.3,57 55.8,59.5 55.8,75 55.8,77.2 57.6,79 76.6,79 78,80.4 78,99.4 76.8,100.6 11.6,100.6 8.5,97.5
PB- on Bottom Layer "Bottom Layer-PB- 1" (solid, pour order 229): 135,10.7 135.8,11.5 137.8,11.5 139.2,12.9 139.2,23.1 138.9,23.4 130.8,23.4 130,24.2 130,43.8 129.7,44.1 126.6,44.1 122.9,40.4 121.365,40.4 119.465,38.5 88.7,38.5 83.7,43.5 68.7,43.5 64.2,39 46,39 45,40 45,48.4 39.8,53.6 21.6,53.6 20.7,53.6 18.3,56 8,56 4.1,59.9 4.1,62 4.1,70.2 4.1,98.3 9.5,103.7 9.501,103.699 79.699,103.699 83.3,107.3 94.4,107.3 95,107.9 95,117.8 93.8,119 17.6,119 17.3,118.7 8.8,110.2 0.7,102.1 0.7,10.8 2,9.5 8.5,9.5 9,9 9,1.5 10,0.5 64,0.5 64.5,1 64.5,5.62 64.88,6 67.3,6 71.3,10 81.7,10 88.7,3 88.7,0.9 89.1,0.5 133.3,0.5 135,2.2
PB- on Bottom Layer "Bottom Layer-PB- 2" (solid, pour order 208): 27.85,67.7 29.8,65.75 29.8,54.762 31.1,53.462 31.1,52.1 29,52.1 28.525,52.575 28.525,58.975 27.4,60.1 20.9,60.1 20.458,60.542 20.458,67.119 21.039,67.7
PBGaN on Bottom Layer "Top Layer-PBGaN" (solid, pour order 177): 86.4,72.2 80.6,78 74.3,78 59.9,78 58,76.1 58,59.8 59.6,58.2 70.4,58.2 76.1,52.5 84.865,52.5 86.4,54.116
EARTH1 on Bottom Layer "Top Layer-EARTH" (solid, pour order 175): 84.2,5.4 84.2,1.3 83.4,0.5 70.3,0.5 69.5,1.3 69.5,5.3 72.5,8.3 81.3,8.3
GND_ISO on Bottom Layer "Bottom Layer-GND_ISO" (solid, pour order 171): 138.5,0.6 138.8,0.3 152.55,0.3 153.5,1.164 153.5,7.5 152.5,8.5 145.1,8.5 139.7,8.5 138.5,7.3
SWNODE1 on Bottom Layer "Bottom Layer-SWNODE1" (solid, pour order 129): 133,100.4 117.4,84.8 117.4,57.15 110.35,50.1 102.335,50.1 98.6,53.835 98.6,60.1 97.6,61.1 91.4,61.1 90.4,60.1 90.4,45.8 93.2,43 119.8,43 126.9,50.1 128.5,50.1 132.3,53.9 132.3,69 154,90.7 154,95.4 149,100.4
NetL1_1 on Bottom Layer "Bottom Layer-NetL1_1" (solid, pour order 133): 164.275,46.675 164.275,78.225 163.6,78.9 155.5,78.9 141.1,64.5 141.1,46.7 142.1,45.7 163.3,45.7
LINE_Filtered1 on Bottom Layer "Bottom Layer-LINE_Filtered1" (solid, pour order 125): 164,44 163.5,44.5 149.7,44.5 147.62,42.42 147.62,21.58 148.7,20.5 154.52,20.5 155.5,21.589 155.5,26.9 157.1,28.5 163.5,28.5 164,29
NEU_Filtered on Bottom Layer "Bottom Layer-NEU_Filtered" (solid, pour order 131): 179.5,14.474 179.5,102.4 162.9,119 104,119 104,109.1 155.9,109.1 169.3,95.7 169.3,73.9 169.3,31.4 173,27.7 173,14.7 174.2,13.5 178.38,13.5
LINE_Filtered on Bottom Layer "Bottom Layer-LINE_Filtered" (solid, pour order 127): 167.5,17 167.5,25.5 167,26 159.5,26 158.5,25 158.5,16 159,15.5 165.7,15.5
NetC10_2 on Bottom Layer "Bottom Layer-NetC10_2" (solid, pour order 94): 145.7,43.9 146.1,43.5 146.1,36.2 143.5,33.6 143.5,29.6 142.576,28.676 136.324,28.676 135.1,29.9 135.1,42.6 136.4,43.9
Idc on Bottom Layer "Bottom Layer-Idc" (solid, pour order 46): 98.9,106 89,106 85.9,106 83,103.1 83,99.4 83,85.4 93.7,74.7 102.4,74.7 106.343,70.757 106.343,64.443 101.7,59.8 101.7,55.3 103.9,53.1 109.067,53.1 114.3,58.267 114.3,90.6
NEU_Filtered on Bottom Layer "Bottom Layer-NetD2_2" (solid, pour order 32): 102.335,68.915 101.55,69.7 91.8,69.7 91.291,69.191 91.291,66.059 92.05,65.3 101.55,65.3 102.335,66.085

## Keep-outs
Keep-Out Layer:
  circle w0.254: c176,116 r7
  circle w0.254: c4,116 r7
  circle w0.254: c3.8,3.9 r7
  lines w0.2: 0.5,8.5 0.5,112 ; 8,119.5 171.5,119.5

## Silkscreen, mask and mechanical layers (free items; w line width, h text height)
Top Overlay:
  lines w0.254: 100.9,1 113.8,1 113.8,8 100.9,8 100.9,1
  text "PB-" at 10.7,103 h1
  text "PB+" at 11.414,95.8 h1
  text "PB-" at 1.6,92.6 h1
  text "PB+" at 33.576,71.3 h1
  text "GaN" at 84.319,64.7 h1
  text "Output" at 83.7,63.275 h1
  text "Idc" at 104.6,62.7 h1
  text "20221212" at 110,50.8 h1.5
  text "SW NODE" at 88.635,49.41 h1
  text "TIDA-010236" at 108.2,48.8 h1.5
  text "Main Board" at 108.475,46.73 h1.5
  text "Rev. B" at 111.015,44.782 h1.5
  text "15V" at 31.6,43.475 h1
  text "Relay" at 79.8,42.2 h1
  text "Iac" at 85.3,42.1 h1
  text "5V" at 36.624,37.536 h1
  text "1.65V" at 100,33.5 h1 r90
  text "12" at 43.036,29.6 h0.8
  text "14" at 44.936,29.519 h0.8
  text "Vdc" at 27.4,29.1 h1
  text "2" at 39.9,29.1 h0.8
  text "PB-" at 7,29 h1
  text "26" at 48.8,29 h0.8
  text "84" at 75.7,29 h0.8
  text "98" at 81.2,29 h0.8
  text "62" at 66.893,28.9 h0.8
  text "112" at 86.9,28.9 h0.8
  text "120" at 89.5,28.9 h0.8
  text "58" at 65.2,28.8 h0.8
  text "34" at 52.3,28.7 h0.8
  text "48" at 57.9,28.7 h0.8
  text "56" at 61.9,28.7 h0.8
  text "FT" at 27.8,26.6 h1
  text "PB-" at 131.265,26.4 h1 r90
  text "PB-" at 2.5,25.3 h1
  text "3.3V" at 125.257,24.549 h1 r90
  text "TEMP" at 27,21.4 h1
  text "VacL" at 124.924,19.85 h1 r90
  text "1" at 40,19.7 h0.8
  text "9" at 43.2,19.6 h0.8
  text "55" at 61.2,19.6 h0.8
  text "17" at 46.1,19.5 h0.8
  text "21" at 47.7,19.5 h0.8
  text "49" at 58.7,19.5 h0.8
  text "89" at 78,19.5 h0.8
  text "99" at 81.873,19.5 h0.8
  text "27" at 50.1,19.4 h0.8
  text "57" at 65.293,19.3 h0.8
  text "69" at 70,19.3 h0.8
  text "45" at 57.168,19 h0.8
  text "119" at 90.6,18.773 h0.8
  text "Vw" at 27.2,16.3 h1
  text "NEU" at 175.5,15.265 h1
  text "LINE" at 163.443,15.173 h1
  text "Vv" at 27.2,13.8 h1
  text "1A" at 34.8,13.7 h1 r90
  text "1B" at 39.9,13.7 h1 r90
  text "2A" at 42.007,13.7 h1 r90
  text "3B" at 50.3,13.642 h1 r90
  text "2B" at 44.9,13.6 h1 r90
  text "3A" at 47.3,13.6 h1 r90
  text "TEMP" at 112.6,12.8 h1 r90
  text "PWMA" at 117.086,12.8 h1 r90
  text "PWMB" at 122.1,12.8 h1 r90
  text "15V" at 33.6,12.6 h1 r90
  text "15V" at 32,12.491 h1 r90
  text "3.3V" at 54,12.3 h1 r90
  text "3.3V" at 55.3,12.3 h1 r90
  text "VacN" at 126.3,11.7 h1 r90
  text "Vu" at 27.4,11.4 h1
  text "/FAULT" at 109.343,10.968 h1 r90
  text "On/Off" at 107.5,9.5 h1
  text "Iw" at 26.6,8.6 h1
  text "Iv" at 26.4,6.2 h1
  text "5V_I" at 152.3,6 h1 r90
  text "RX" at 124.7,5.7 h1 r90
  text "GND_I" at 144.8,5.6 h1 r90
  text "Iu" at 26.6,3.8 h1
  text "TX" at 124.7,2.2 h1 r90
  text "EARTH" at 157.3,1.9 h1
  text "RX" at 153.1,1.55 h1
  text "NTC Heatsink" at 63.7,0.7 h0.8
  text "TX" at 137.2,0.4 h1
Top Solder:
  rectangle: 106.075,65.025 110.25,68.675
  rectangle: 98.3,65.025 102.75,68.675
  rectangle: 90.8,65.75 95.9,68.675
  rectangle: 80.8,65.35 85.25,68.675
Bottom Solder:
  region: 47.51,62.325 41.51,62.325 41.51,56.875 47.51,56.875
  region: 65.29,64.725 59.29,64.725 59.29,59.225 65.29,59.225
Mechanical 1:
  lines w0.2: 0,3 ccw(c3,3) 3,0 157,0 177,0 ccw(c177,3) 180,3 180,117 ccw(c177,117) 177,120 157,120 13,120 3,120 ccw(c3,117) 0,117 0,3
